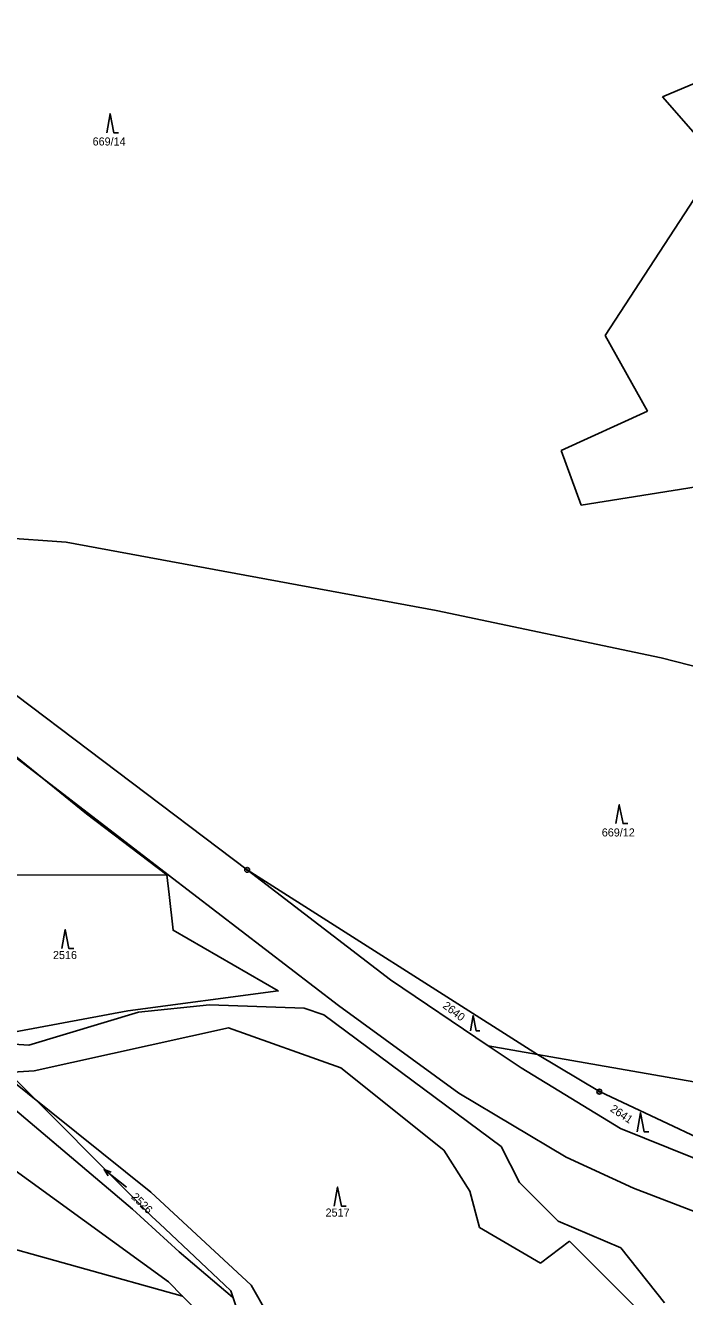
# Model space of a CAD drawing. Extents: x -546762 to -540209, y -1046851 to -1035694.
# Drawn here: x -542246.2 to -542107.3, y -1040002.5 to -1039734.4 of the extents above; entities that cross this region are included whole.
import ezdxf

# ---------------------------------------------------------------- set-up
doc = ezdxf.new("R2010")
doc.units = 0
for name, color, linetype in [('Vrstva 1', 7, 'Continuous'), ('Vrstva 18', 7, 'Continuous'), ('Vrstva 24', 7, 'Continuous'), ('Vrstva 25', 7, 'Continuous'), ('Vrstva 52', 7, 'Continuous'), ('Vrstva 6', 7, 'Continuous')]:
    doc.layers.add(name, color=color, linetype=linetype)

msp = doc.modelspace()

# ---------------------------------------------------------------- linework, layer by layer
at = {"layer": 'Vrstva 1'}
for points in [[(-542297.11, -1039851.23), (-542216.14, -1039913.5)], [(-542199.5, -1039912.48), (-542254.27, -1039871.15)], [(-542216.14, -1039913.5), (-542277.66, -1039913.61)], [(-542180.24, -1039941.1), (-542216.14, -1039913.5)], [(-542199.5, -1039912.48), (-542169.28, -1039935.65)], [(-542138.26, -1039951.38), (-542199.5, -1039912.48)], [(-542169.28, -1039935.65), (-542148.67, -1039949.56)], [(-542222.42, -1039942.48), (-542207.42, -1039940.91)], [(-542207.42, -1039940.91), (-542187.46, -1039941.65)], [(-542154.86, -1039959.54), (-542180.24, -1039941.1)], [(-542245.5, -1039949.45), (-542222.42, -1039942.48)], [(-542187.46, -1039941.65), (-542183.31, -1039943.04)], [(-542183.31, -1039943.04), (-542145.96, -1039970.8)], [(-542203.41, -1039945.8), (-542244.42, -1039954.89)], [(-542179.75, -1039954.24), (-542203.41, -1039945.8)], [(-542259.27, -1039948.54), (-542245.5, -1039949.45)], [(-542141.72, -1039954.24), (-542148.67, -1039949.56)], [(-542148.67, -1039949.56), (-542138.26, -1039951.38)], [(-542138.26, -1039951.38), (-542125.25, -1039959.25)], [(-542213.14, -1040002.36), (-542390.31, -1039952.9)], [(-542244.42, -1039954.89), (-542251.17, -1039955.26)], [(-542158.06, -1039971.61), (-542179.75, -1039954.24)], [(-542120.76, -1039966.99), (-542141.72, -1039954.24)], [(-542257.29, -1039955.6), (-542223.67, -1039984.04)], [(-542251.17, -1039955.26), (-542219.78, -1039980.45)], [(-542132.26, -1039973.05), (-542154.86, -1039959.54)], [(-542125.25, -1039959.25), (-542090.32, -1039975.65)], [(-542100.56, -1039975.2), (-542120.76, -1039966.99)], [(-542145.96, -1039970.8), (-542142.09, -1039978.39)], [(-542251.47, -1039973.65), (-542216.1, -1039999.37)], [(-542152.56, -1039980.25), (-542158.06, -1039971.61)], [(-542118.02, -1039979.63), (-542132.26, -1039973.05)], [(-542142.09, -1039978.39), (-542133.9, -1039986.56)], [(-542219.78, -1039980.45), (-542198.67, -1040000.04)], [(-542150.54, -1039987.87), (-542152.56, -1039980.25)], [(-542098.44, -1039987.13), (-542118.02, -1039979.63)], [(-542223.67, -1039984.04), (-542213.85, -1039993.06)], [(-542133.9, -1039986.56), (-542120.74, -1039992.2)], [(-542137.65, -1039995.4), (-542150.54, -1039987.87)], [(-542131.51, -1039990.77), (-542137.65, -1039995.4)], [(-542117.81, -1040004.51), (-542131.51, -1039990.77)], [(-542120.74, -1039992.2), (-542111.54, -1040003.8)], [(-542213.85, -1039993.06), (-542202.62, -1040002.56)], [(-542216.1, -1039999.37), (-542213.14, -1040002.36)], [(-542198.67, -1040000.04), (-542195.21, -1040006.11)], [(-542209.09, -1040006.46), (-542213.14, -1040002.36)]]:
    msp.add_lwpolyline(points, dxfattribs=at)
at = {"layer": 'Vrstva 24'}
for centre, radius in [((-542199.5, -1039912.48), 0.5), ((-542199.5, -1039912.48), 0.1), ((-542125.25, -1039959.25), 0.5), ((-542125.25, -1039959.25), 0.1)]:
    msp.add_circle(centre, radius, dxfattribs=at)
at = {"layer": 'Vrstva 25'}
for points in [[(-542229.11, -1039757.04), (-542228.41, -1039753.04), (-542227.61, -1039757.04), (-542226.61, -1039757.04)], [(-542121.76, -1039902.74), (-542121.06, -1039898.74), (-542120.26, -1039902.74), (-542119.26, -1039902.74)], [(-542238.56, -1039929.08), (-542237.86, -1039925.08), (-542237.06, -1039929.08), (-542236.06, -1039929.08)], [(-542152.44, -1039946.42), (-542151.88, -1039943.22), (-542151.24, -1039946.42), (-542150.44, -1039946.42)], [(-542117.3, -1039967.7), (-542116.6, -1039963.7), (-542115.8, -1039967.7), (-542114.8, -1039967.7)], [(-542224.97, -1039979.4), (-542229.67, -1039975.68), (-542228.81, -1039977)], [(-542229.67, -1039975.68), (-542228.18, -1039976.22)], [(-542181.13, -1039983.38), (-542180.43, -1039979.38), (-542179.63, -1039983.38), (-542178.63, -1039983.38)]]:
    msp.add_lwpolyline(points, dxfattribs=at)
at = {"layer": 'Vrstva 52'}
msp.add_lwpolyline([(-542201.89, -1040004.43), (-542202.94, -1040001.27), (-542204.29, -1040000), (-542216.78, -1039988.21), (-542217.91, -1039987.15), (-542219.57, -1039985.58), (-542220.27, -1039984.88), (-542223.54, -1039981.6), (-542233.42, -1039971.67), (-542237.25, -1039967.82), (-542238.45, -1039966.61), (-542250.49, -1039954.52), (-542252.4, -1039952.6), (-542256.81, -1039948.17), (-542253.01, -1039947.47), (-542224.62, -1039942.22), (-542192.94, -1039938), (-542215.11, -1039925.2), (-542215.97, -1039917.69), (-542216.44, -1039913.53), (-542233.34, -1039900.68), (-542264.49, -1039875.43)], dxfattribs=at)
at = {"layer": 'Vrstva 6'}
for points in [[(-542111.94, -1039749.45), (-542076.2, -1039734.42)], [(-542111.94, -1039749.45), (-542100.05, -1039763.04)], [(-542100.05, -1039763.04), (-542124.03, -1039799.83)], [(-542124.03, -1039799.83), (-542115.13, -1039815.78)], [(-542115.13, -1039815.78), (-542133.3, -1039824.08)], [(-542133.3, -1039824.08), (-542129.07, -1039835.58)], [(-542129.07, -1039835.58), (-542085.47, -1039828.65)], [(-542265.4, -1039841.38), (-542237.68, -1039843.35)], [(-542237.68, -1039843.35), (-542159.65, -1039857.82)], [(-542159.65, -1039857.82), (-542112.18, -1039867.79)], [(-542112.18, -1039867.79), (-542065.25, -1039879.78)], [(-542100.91, -1039957.93), (-542138.26, -1039951.38)]]:
    msp.add_lwpolyline(points, dxfattribs=at)

# ---------------------------------------------------------------- texts
at = {"layer": 'Vrstva 18'}
for s, p in [('669/14', (-542232.08, -1039759.74)), ('669/12', (-542124.73, -1039905.44)), ('2516', (-542240.44, -1039931.29)), ('2517', (-542182.96, -1039985.59))]:
    msp.add_text(s, height=1.7, dxfattribs=at).set_placement(p)
for s, rotation, p in [('2640', 322.4033, (-542158.41, -1039941.42)), ('2641', 326.2995, (-542123.12, -1039963.26)), ('2526', 315.6424, (-542224.06, -1039981.61))]:
    msp.add_text(s, height=1.7, rotation=rotation, dxfattribs=at).set_placement(p)

doc.saveas('drawing.dxf')
